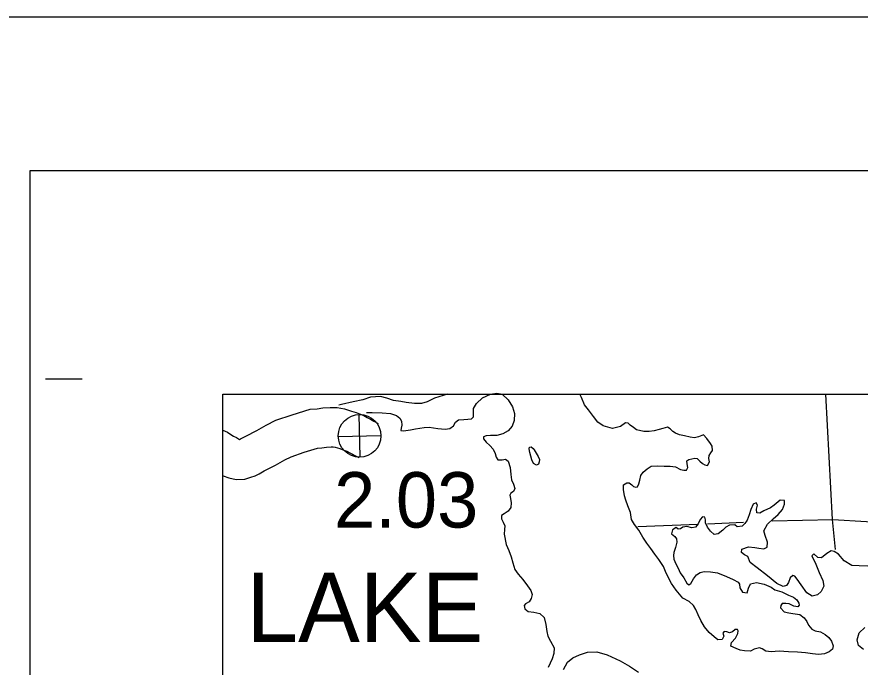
# Model space of a CAD drawing. Extents: x 22866 to 28196, y 1324810 to 1328105.
# Drawn here: x 23880.5 to 24094.2, y 1327377.1 to 1327541.9 of the extents above; entities that cross this region are included whole.
import ezdxf

# ---------------------------------------------------------------- set-up
doc = ezdxf.new("R2010")
doc.units = 0
for name, color, linetype in [('Level 10', 7, 'Continuous'), ('Level 25', 7, 'Continuous'), ('Level 26', 7, 'Continuous'), ('Level 5', 7, 'Continuous'), ('Level 7', 7, 'Continuous'), ('Level 9', 7, 'Continuous'), ('R_Border', 7, 'Continuous'), ('R_No Plot', 7, 'Continuous')]:
    doc.layers.add(name, color=color, linetype=linetype)

msp = doc.modelspace()

# ---------------------------------------------------------------- linework, layer by layer
at = {"layer": 'Level 10'}
for points in [[(23932.69, 1327437.11), (23933.86, 1327436.62), (23935.03, 1327435.9), (23935.43, 1327435.63), (23936.18, 1327435.25), (23936.91, 1327434.82), (23937.22, 1327434.91), (23938.53, 1327435.65), (23941.35, 1327437.05), (23943.68, 1327438.39), (23946.13, 1327439.65), (23950.26, 1327441.02), (23954.87, 1327442.45), (23956.63, 1327442.58), (23958.02, 1327442.8), (23959.89, 1327442.89), (23961.72, 1327442.89), (23963.53, 1327442.52), (23965.36, 1327442), (23966.49, 1327441.61), (23967.37, 1327441.25), (23968.41, 1327440.83), (23969.3, 1327440.35), (23970.16, 1327439.97), (23971.01, 1327439.46), (23972.08, 1327438.85)], [(23932.69, 1327437.11), (23933.86, 1327436.62), (23935.03, 1327435.9), (23935.43, 1327435.63), (23936.18, 1327435.25), (23936.91, 1327434.82), (23937.22, 1327434.91), (23938.53, 1327435.65), (23941.35, 1327437.05), (23943.68, 1327438.39), (23946.13, 1327439.65), (23950.26, 1327441.02), (23954.87, 1327442.45), (23956.63, 1327442.58), (23958.02, 1327442.8), (23959.89, 1327442.89), (23961.72, 1327442.89), (23963.53, 1327442.52), (23965.36, 1327442), (23966.49, 1327441.61), (23967.37, 1327441.25), (23968.41, 1327440.83), (23969.3, 1327440.35), (23970.16, 1327439.97), (23971.01, 1327439.46), (23972.08, 1327438.85)], [(23932.69, 1327425.69), (23932.83, 1327425.6), (23934.2, 1327425.04), (23936.11, 1327424.62), (23938.28, 1327424.77), (23939.78, 1327425.27), (23940.89, 1327425.59), (23941.89, 1327426.1), (23943.19, 1327426.83), (23946.07, 1327428.25), (23948.45, 1327429.63), (23950, 1327430.42), (23953.31, 1327431.53), (23956.75, 1327432.59), (23957.77, 1327432.67), (23959.03, 1327432.86), (23960.14, 1327432.92), (23960.7, 1327432.92), (23961.17, 1327432.82), (23962.35, 1327432.49), (23962.97, 1327432.27), (23963.64, 1327432), (23964.14, 1327431.8), (23964.87, 1327431.4), (23965.56, 1327431.09), (23965.99, 1327430.84), (23967.15, 1327430.18)], [(23932.69, 1327425.69), (23932.83, 1327425.6), (23934.2, 1327425.04), (23936.11, 1327424.62), (23938.28, 1327424.77), (23939.78, 1327425.27), (23940.89, 1327425.59), (23941.89, 1327426.1), (23943.19, 1327426.83), (23946.07, 1327428.25), (23948.45, 1327429.63), (23950, 1327430.42), (23953.31, 1327431.53), (23956.75, 1327432.59), (23957.77, 1327432.67), (23959.03, 1327432.86), (23960.14, 1327432.92), (23960.7, 1327432.92), (23961.17, 1327432.82), (23962.35, 1327432.49), (23962.97, 1327432.27), (23963.64, 1327432), (23964.14, 1327431.8), (23964.87, 1327431.4), (23965.56, 1327431.09), (23965.99, 1327430.84), (23967.15, 1327430.18)]]:
    msp.add_lwpolyline(points, dxfattribs=at)
at = {"layer": 'Level 26'}
for p, q in [((23967.52, 1327430.29), (23967.27, 1327441.11)), ((23967.52, 1327430.29), (23967.27, 1327441.11)), ((23961.98, 1327435.58), (23972.8, 1327435.83)), ((23961.98, 1327435.58), (23972.8, 1327435.83))]:
    msp.add_line(p, q, dxfattribs=at)
msp.add_circle((23967.39, 1327435.7), 5.41, dxfattribs=at)
msp.add_circle((23967.39, 1327435.7), 5.41, dxfattribs=at)
at = {"layer": 'Level 5'}
for points in [[(24085.48, 1327446.26), (24087.12, 1327414.51), (24087.9, 1327406.87)], [(24085.48, 1327446.26), (24087.12, 1327414.51), (24087.9, 1327406.87)], [(24164.15, 1327409.88), (24087.29, 1327414.41), (24071.91, 1327414.08)], [(24164.15, 1327409.88), (24087.29, 1327414.41), (24071.91, 1327414.08)], [(24053.06, 1327413.25), (24037.92, 1327412.66)], [(24053.06, 1327413.25), (24037.92, 1327412.66)], [(24064.64, 1327413.78), (24055.58, 1327413.29)], [(24064.64, 1327413.78), (24055.58, 1327413.29)]]:
    msp.add_lwpolyline(points, dxfattribs=at)
at = {"layer": 'Level 7'}
msp.add_lwpolyline([(23897.05, 1327450.11), (23887.75, 1327450.07)], dxfattribs=at)
at = {"layer": 'Level 9'}
for points in [[(23969.14, 1327441.6), (23970.58, 1327441.66), (23973.11, 1327441.55), (23975.21, 1327441.39), (23976.75, 1327440.89), (23977.56, 1327440.15), (23977.98, 1327439.39), (23978.1, 1327438.42), (23977.95, 1327437.66), (23977.83, 1327437.05), (23978.53, 1327436.97), (23980.28, 1327437.27), (23981.58, 1327437.47), (23983.73, 1327437.85), (23985.03, 1327437.91), (23987.2, 1327437.55), (23989.09, 1327437.39), (23990.25, 1327437.55), (23991.17, 1327438.27), (23991.72, 1327439.15), (23992.47, 1327439.73), (23993.83, 1327439.86), (23994.83, 1327439.95), (23995.75, 1327440.03), (23996.28, 1327440.55), (23996.28, 1327441.78), (23996.23, 1327442.68), (23996.97, 1327443.92), (23998.53, 1327445.32), (24000.58, 1327446.27), (24002.17, 1327446.5), (24003.47, 1327446.26), (24005.06, 1327444.83), (24006.1, 1327443.09), (24006.6, 1327441.37), (24006.54, 1327439.63), (24006.07, 1327438.19), (24005, 1327437), (24003.72, 1327436.24), (24002.16, 1327435.81), (24000.57, 1327435.81), (23999.44, 1327435.68), (23998.78, 1327435.5), (23998.76, 1327434.97), (23999.44, 1327434.08), (24000.36, 1327433.27), (24001.21, 1327432.36), (24001.73, 1327431.27), (24001.95, 1327430.27), (24002.43, 1327429.62), (24003.49, 1327429.67), (24004.32, 1327429.76), (24005, 1327429.27), (24005.56, 1327427.72), (24005.7, 1327425.89), (24005.86, 1327424.53)], [(23969.14, 1327441.6), (23970.58, 1327441.66), (23973.11, 1327441.55), (23975.21, 1327441.39), (23976.75, 1327440.89), (23977.56, 1327440.15), (23977.98, 1327439.39), (23978.1, 1327438.42), (23977.95, 1327437.66), (23977.83, 1327437.05), (23978.53, 1327436.97), (23980.28, 1327437.27), (23981.58, 1327437.47), (23983.73, 1327437.85), (23985.03, 1327437.91), (23987.2, 1327437.55), (23989.09, 1327437.39), (23990.25, 1327437.55), (23991.17, 1327438.27), (23991.72, 1327439.15), (23992.47, 1327439.73), (23993.83, 1327439.86), (23994.83, 1327439.95), (23995.75, 1327440.03), (23996.28, 1327440.55), (23996.28, 1327441.78), (23996.23, 1327442.68), (23996.97, 1327443.92), (23998.53, 1327445.32), (24000.58, 1327446.27), (24002.17, 1327446.5), (24003.47, 1327446.26), (24005.06, 1327444.83), (24006.1, 1327443.09), (24006.6, 1327441.37), (24006.54, 1327439.63), (24006.07, 1327438.19), (24005, 1327437), (24003.72, 1327436.24), (24002.16, 1327435.81), (24000.57, 1327435.81), (23999.44, 1327435.68), (23998.78, 1327435.5), (23998.76, 1327434.97), (23999.44, 1327434.08), (24000.36, 1327433.27), (24001.21, 1327432.36), (24001.73, 1327431.27), (24001.95, 1327430.27), (24002.43, 1327429.62), (24003.49, 1327429.67), (24004.32, 1327429.76), (24005, 1327429.27), (24005.56, 1327427.72), (24005.7, 1327425.89), (24005.86, 1327424.53)], [(23989.54, 1327446.26), (23988.54, 1327445.94), (23986.4, 1327445.26), (23984.52, 1327444.29), (23983.04, 1327443.89), (23981.27, 1327443.89), (23979.17, 1327444.18), (23977.8, 1327444.38), (23975.97, 1327444.64), (23974.26, 1327445.27), (23972.69, 1327445.67), (23970.16, 1327445.48), (23968.22, 1327444.81), (23965.77, 1327444.32), (23962.79, 1327443.66), (23962.09, 1327443.47)], [(23989.54, 1327446.26), (23988.54, 1327445.94), (23986.4, 1327445.26), (23984.52, 1327444.29), (23983.04, 1327443.89), (23981.27, 1327443.89), (23979.17, 1327444.18), (23977.8, 1327444.38), (23975.97, 1327444.64), (23974.26, 1327445.27), (23972.69, 1327445.67), (23970.16, 1327445.48), (23968.22, 1327444.81), (23965.77, 1327444.32), (23962.79, 1327443.66), (23962.09, 1327443.47)], [(24025.43, 1327442.34), (24024.38, 1327443.58), (24023.6, 1327445.46), (24023.22, 1327446.26)], [(24025.43, 1327442.34), (24024.38, 1327443.58), (24023.6, 1327445.46), (24023.22, 1327446.26)], [(24063.14, 1327386.65), (24062.58, 1327386.6), (24061.86, 1327386.02), (24061.13, 1327385.8), (24060.46, 1327386.06), (24059.76, 1327386.14), (24059.41, 1327385.67), (24059.69, 1327384.91), (24059.24, 1327384.13), (24058.18, 1327383.98), (24057.23, 1327384.75), (24055.94, 1327385.86), (24054.75, 1327387.33), (24053.85, 1327388.88), (24053.15, 1327390.33), (24052.63, 1327391.68), (24052.01, 1327392.74), (24050.89, 1327393.71), (24049.34, 1327394.61), (24047.57, 1327396.61), (24046.43, 1327398.28), (24045.11, 1327400.92), (24044.41, 1327402.63), (24043.18, 1327404.34), (24042.22, 1327405.69), (24041.15, 1327407.16), (24040.16, 1327408.51), (24039.2, 1327410.02), (24038.13, 1327411.79), (24037.03, 1327413.24), (24036.27, 1327414.49), (24036, 1327416.31), (24035.34, 1327417.96), (24034.84, 1327419.39), (24034.55, 1327420.51), (24034.22, 1327422.1), (24034.22, 1327423.27), (24035.08, 1327423.82), (24035.74, 1327423.8), (24036.38, 1327423.32), (24036.76, 1327422.89), (24037.43, 1327422.71), (24037.79, 1327422.78), (24038.11, 1327423.55), (24038.39, 1327424.46), (24038.69, 1327425.66), (24039.27, 1327426.51), (24040.29, 1327427.36), (24041.3, 1327428.02), (24042.86, 1327428.12), (24044.53, 1327428.05), (24046.06, 1327427.99), (24047.46, 1327427.88), (24048.74, 1327427.21), (24049.54, 1327427.03), (24050.2, 1327427.01), (24050.59, 1327427.72), (24050.4, 1327428.61), (24050.29, 1327429.38), (24050.81, 1327429.72), (24051.54, 1327429.9), (24052.3, 1327430.05), (24052.93, 1327429.97), (24053.58, 1327429.31), (24054.29, 1327428.66), (24054.86, 1327428.34), (24055.53, 1327428.16), (24056.08, 1327429.13), (24055.93, 1327429.93), (24055.98, 1327430.7), (24056.43, 1327431.37), (24056.78, 1327432.01), (24056.72, 1327433.08), (24056.28, 1327433.8), (24055.35, 1327435.05), (24054.57, 1327435.96), (24053.28, 1327435.5), (24052.26, 1327435.21), (24051.19, 1327435.36), (24049.68, 1327435.73), (24048.42, 1327435.93), (24047.44, 1327436.41), (24046.8, 1327436.8), (24046.09, 1327437.45), (24045.42, 1327437.87), (24044.26, 1327437.61), (24043.33, 1327437.32), (24042.01, 1327436.96), (24040.75, 1327436.83), (24039.39, 1327436.84), (24037.58, 1327437.23), (24036.77, 1327437.81), (24035.96, 1327438.43), (24035.45, 1327438.95), (24034.78, 1327438.97), (24033.54, 1327438.08), (24031.49, 1327437.53), (24029.08, 1327438.22), (24027.76, 1327439.19), (24026.7, 1327440.63), (24025.43, 1327442.34)], [(24063.14, 1327386.65), (24062.58, 1327386.6), (24061.86, 1327386.02), (24061.13, 1327385.8), (24060.46, 1327386.06), (24059.76, 1327386.14), (24059.41, 1327385.67), (24059.69, 1327384.91), (24059.24, 1327384.13), (24058.18, 1327383.98), (24057.23, 1327384.75), (24055.94, 1327385.86), (24054.75, 1327387.33), (24053.85, 1327388.88), (24053.15, 1327390.33), (24052.63, 1327391.68), (24052.01, 1327392.74), (24050.89, 1327393.71), (24049.34, 1327394.61), (24047.57, 1327396.61), (24046.43, 1327398.28), (24045.11, 1327400.92), (24044.41, 1327402.63), (24043.18, 1327404.34), (24042.22, 1327405.69), (24041.15, 1327407.16), (24040.16, 1327408.51), (24039.2, 1327410.02), (24038.13, 1327411.79), (24037.03, 1327413.24), (24036.27, 1327414.49), (24036, 1327416.31), (24035.34, 1327417.96), (24034.84, 1327419.39), (24034.55, 1327420.51), (24034.22, 1327422.1), (24034.22, 1327423.27), (24035.08, 1327423.82), (24035.74, 1327423.8), (24036.38, 1327423.32), (24036.76, 1327422.89), (24037.43, 1327422.71), (24037.79, 1327422.78), (24038.11, 1327423.55), (24038.39, 1327424.46), (24038.69, 1327425.66), (24039.27, 1327426.51), (24040.29, 1327427.36), (24041.3, 1327428.02), (24042.86, 1327428.12), (24044.53, 1327428.05), (24046.06, 1327427.99), (24047.46, 1327427.88), (24048.74, 1327427.21), (24049.54, 1327427.03), (24050.2, 1327427.01), (24050.59, 1327427.72), (24050.4, 1327428.61), (24050.29, 1327429.38), (24050.81, 1327429.72), (24051.54, 1327429.9), (24052.3, 1327430.05), (24052.93, 1327429.97), (24053.58, 1327429.31), (24054.29, 1327428.66), (24054.86, 1327428.34), (24055.53, 1327428.16), (24056.08, 1327429.13), (24055.93, 1327429.93), (24055.98, 1327430.7), (24056.43, 1327431.37), (24056.78, 1327432.01), (24056.72, 1327433.08), (24056.28, 1327433.8), (24055.35, 1327435.05), (24054.57, 1327435.96), (24053.28, 1327435.5), (24052.26, 1327435.21), (24051.19, 1327435.36), (24049.68, 1327435.73), (24048.42, 1327435.93), (24047.44, 1327436.41), (24046.8, 1327436.8), (24046.09, 1327437.45), (24045.42, 1327437.87), (24044.26, 1327437.61), (24043.33, 1327437.32), (24042.01, 1327436.96), (24040.75, 1327436.83), (24039.39, 1327436.84), (24037.58, 1327437.23), (24036.77, 1327437.81), (24035.96, 1327438.43), (24035.45, 1327438.95), (24034.78, 1327438.97), (24033.54, 1327438.08), (24031.49, 1327437.53), (24029.08, 1327438.22), (24027.76, 1327439.19), (24026.7, 1327440.63), (24025.43, 1327442.34)], [(24012.62, 1327430.44), (24013, 1327429.71), (24012.91, 1327429.14), (24012.73, 1327428.54), (24012.2, 1327428.29), (24011.43, 1327428.68), (24011.01, 1327429.6), (24010.76, 1327430.53), (24010.54, 1327431.46), (24010.35, 1327432.39), (24010.41, 1327432.82), (24010.9, 1327432.93), (24011.35, 1327432.51), (24011.62, 1327432.18)], [(24012.62, 1327430.44), (24013, 1327429.71), (24012.91, 1327429.14), (24012.73, 1327428.54), (24012.2, 1327428.29), (24011.43, 1327428.68), (24011.01, 1327429.6), (24010.76, 1327430.53), (24010.54, 1327431.46), (24010.35, 1327432.39), (24010.41, 1327432.82), (24010.9, 1327432.93), (24011.35, 1327432.51), (24011.62, 1327432.18)], [(24011.62, 1327432.18), (24012.62, 1327430.44)], [(24011.62, 1327432.18), (24012.62, 1327430.44)], [(24005.86, 1327424.53), (24006.42, 1327423.44), (24006.71, 1327422.35), (24006.39, 1327421.64), (24005.7, 1327421.16), (24005.45, 1327420.66), (24005.6, 1327419.79), (24005.82, 1327418.7), (24005.68, 1327417.56), (24005.04, 1327416.65), (24004.05, 1327415.96), (24003.3, 1327415.55), (24003.35, 1327414.65), (24003.77, 1327413.82), (24004.22, 1327412.93), (24004.11, 1327411.97), (24004.03, 1327410.76), (24004.52, 1327408.21), (24005.22, 1327406.63), (24005.75, 1327405.07), (24006.25, 1327403.52), (24006.75, 1327401.86), (24007.57, 1327400.68), (24008.77, 1327399.31), (24009.97, 1327397.67), (24010.76, 1327396.52), (24011.08, 1327395.53), (24010.87, 1327394.52), (24010.32, 1327393.68), (24009.4, 1327393.13), (24009.08, 1327392.72), (24009.23, 1327391.89), (24010.07, 1327391.21), (24011.54, 1327391.01), (24013.04, 1327390.64), (24014.16, 1327389.7), (24014.57, 1327387.87), (24014.87, 1327386.11), (24015.06, 1327384.92), (24015.72, 1327383.67), (24016.66, 1327381.99), (24016.62, 1327380.52), (24016.15, 1327379.21), (24015.2, 1327376.96)], [(24005.86, 1327424.53), (24006.42, 1327423.44), (24006.71, 1327422.35), (24006.39, 1327421.64), (24005.7, 1327421.16), (24005.45, 1327420.66), (24005.6, 1327419.79), (24005.82, 1327418.7), (24005.68, 1327417.56), (24005.04, 1327416.65), (24004.05, 1327415.96), (24003.3, 1327415.55), (24003.35, 1327414.65), (24003.77, 1327413.82), (24004.22, 1327412.93), (24004.11, 1327411.97), (24004.03, 1327410.76), (24004.52, 1327408.21), (24005.22, 1327406.63), (24005.75, 1327405.07), (24006.25, 1327403.52), (24006.75, 1327401.86), (24007.57, 1327400.68), (24008.77, 1327399.31), (24009.97, 1327397.67), (24010.76, 1327396.52), (24011.08, 1327395.53), (24010.87, 1327394.52), (24010.32, 1327393.68), (24009.4, 1327393.13), (24009.08, 1327392.72), (24009.23, 1327391.89), (24010.07, 1327391.21), (24011.54, 1327391.01), (24013.04, 1327390.64), (24014.16, 1327389.7), (24014.57, 1327387.87), (24014.87, 1327386.11), (24015.06, 1327384.92), (24015.72, 1327383.67), (24016.66, 1327381.99), (24016.62, 1327380.52), (24016.15, 1327379.21), (24015.2, 1327376.96)], [(24096.22, 1327402.64), (24093.99, 1327402.76), (24092.09, 1327402.86), (24090.2, 1327404.05), (24088.74, 1327405.68), (24087.66, 1327406.36), (24086.86, 1327406.57), (24085.81, 1327405.92), (24084.47, 1327404.79), (24083.54, 1327404.87), (24082.52, 1327405.82), (24081.96, 1327405.3), (24082.97, 1327403.16), (24083.88, 1327401.08), (24084.82, 1327399.07), (24085.05, 1327397.64), (24084.39, 1327396.26), (24083.44, 1327395.41), (24082.12, 1327395.08), (24080.74, 1327395.88), (24079.26, 1327397.92), (24078.3, 1327399.4), (24077.72, 1327400.18), (24077.18, 1327400.34), (24076.5, 1327399.76), (24076.12, 1327398.52), (24075.54, 1327397.77), (24074.75, 1327397.52), (24073.1, 1327398.32), (24070.77, 1327400.2), (24068.16, 1327402.24), (24066.37, 1327403.57), (24065.77, 1327405.09), (24064.96, 1327405.57), (24064.15, 1327406.16), (24064.27, 1327406.99), (24065.92, 1327407.59), (24067.55, 1327407.43), (24068.59, 1327407.25), (24069.85, 1327407.11), (24070.71, 1327407.53), (24070.75, 1327408.76), (24070.15, 1327410.41), (24069.86, 1327411.61), (24070.75, 1327413.33), (24072.22, 1327414.66), (24073.49, 1327415.78), (24074.56, 1327417.07), (24075.1, 1327418.41), (24075.04, 1327419.28), (24073.98, 1327419.42), (24072.41, 1327418.12), (24071.49, 1327417.47), (24069.81, 1327416.67), (24068.8, 1327416.08), (24068.06, 1327416.2), (24068.01, 1327417.13), (24068.25, 1327418.17), (24067.87, 1327418.69), (24067.12, 1327418.38), (24066.51, 1327417), (24066.08, 1327415.66), (24065.57, 1327414.35), (24064.99, 1327413.5), (24064.31, 1327412.82), (24063.05, 1327412.63), (24062.47, 1327413.15), (24061.15, 1327413.05), (24060.19, 1327412.53), (24059.41, 1327411.82), (24058.27, 1327410.89), (24057.27, 1327410.74), (24056.29, 1327411.55)], [(24096.22, 1327402.64), (24093.99, 1327402.76), (24092.09, 1327402.86), (24090.2, 1327404.05), (24088.74, 1327405.68), (24087.66, 1327406.36), (24086.86, 1327406.57), (24085.81, 1327405.92), (24084.47, 1327404.79), (24083.54, 1327404.87), (24082.52, 1327405.82), (24081.96, 1327405.3), (24082.97, 1327403.16), (24083.88, 1327401.08), (24084.82, 1327399.07), (24085.05, 1327397.64), (24084.39, 1327396.26), (24083.44, 1327395.41), (24082.12, 1327395.08), (24080.74, 1327395.88), (24079.26, 1327397.92), (24078.3, 1327399.4), (24077.72, 1327400.18), (24077.18, 1327400.34), (24076.5, 1327399.76), (24076.12, 1327398.52), (24075.54, 1327397.77), (24074.75, 1327397.52), (24073.1, 1327398.32), (24070.77, 1327400.2), (24068.16, 1327402.24), (24066.37, 1327403.57), (24065.77, 1327405.09), (24064.96, 1327405.57), (24064.15, 1327406.16), (24064.27, 1327406.99), (24065.92, 1327407.59), (24067.55, 1327407.43), (24068.59, 1327407.25), (24069.85, 1327407.11), (24070.71, 1327407.53), (24070.75, 1327408.76), (24070.15, 1327410.41), (24069.86, 1327411.61), (24070.75, 1327413.33), (24072.22, 1327414.66), (24073.49, 1327415.78), (24074.56, 1327417.07), (24075.1, 1327418.41), (24075.04, 1327419.28), (24073.98, 1327419.42), (24072.41, 1327418.12), (24071.49, 1327417.47), (24069.81, 1327416.67), (24068.8, 1327416.08), (24068.06, 1327416.2), (24068.01, 1327417.13), (24068.25, 1327418.17), (24067.87, 1327418.69), (24067.12, 1327418.38), (24066.51, 1327417), (24066.08, 1327415.66), (24065.57, 1327414.35), (24064.99, 1327413.5), (24064.31, 1327412.82), (24063.05, 1327412.63), (24062.47, 1327413.15), (24061.15, 1327413.05), (24060.19, 1327412.53), (24059.41, 1327411.82), (24058.27, 1327410.89), (24057.27, 1327410.74), (24056.29, 1327411.55)], [(24056.29, 1327411.55), (24055.54, 1327412.6), (24055.01, 1327413.65), (24055.03, 1327414.42), (24054.88, 1327415.08), (24054.25, 1327415.14), (24053.73, 1327414.53), (24053.19, 1327413.38), (24052.54, 1327412.54), (24051.58, 1327412.38), (24050.31, 1327412.69), (24049.28, 1327412.57), (24048.69, 1327412.15), (24048.13, 1327412.04), (24047.59, 1327412.46), (24046.64, 1327411.88), (24046.46, 1327410.91), (24047.24, 1327410.19), (24047.72, 1327409.63), (24047.74, 1327408.77), (24047.43, 1327407.43), (24047.03, 1327406.16), (24046.95, 1327405.35), (24047.06, 1327404.49), (24047.49, 1327403.27), (24048.08, 1327402.21), (24048.6, 1327401.03), (24049.56, 1327399.75), (24050.35, 1327398.37), (24050.8, 1327397.94), (24051.32, 1327398.25), (24051.99, 1327399.43), (24052.77, 1327400.45), (24053.72, 1327401.04), (24054.68, 1327401.29), (24056.34, 1327401.26), (24058.05, 1327400.96), (24060.39, 1327400.08), (24062.07, 1327399.32), (24063.32, 1327398.61), (24063.63, 1327398.12), (24063.72, 1327397.15), (24064.44, 1327396.13), (24065.57, 1327395.89), (24065.91, 1327397.13), (24066.42, 1327398.24), (24068.01, 1327398.51), (24069.95, 1327398.12), (24071.69, 1327397.32), (24072.6, 1327396.68), (24074.35, 1327396.15), (24076.09, 1327395.35), (24077.37, 1327394.78), (24078.15, 1327394.16), (24078.73, 1327393.34), (24078.77, 1327392.78), (24078.45, 1327392.37), (24077.42, 1327392.55), (24076.24, 1327393.12), (24075.41, 1327393.2), (24074.51, 1327393.19), (24074.12, 1327392.74), (24074.07, 1327392.08), (24074.95, 1327391.1), (24076.15, 1327390.86), (24077.19, 1327390.68), (24078.99, 1327390.45), (24080.04, 1327389.61), (24080.69, 1327388.69), (24081.11, 1327387.76), (24082, 1327386.72), (24082.84, 1327386.3), (24084.21, 1327386.06), (24085.35, 1327385.32), (24086.3, 1327384.61), (24086.98, 1327383.66), (24087.44, 1327382.47), (24087.26, 1327381.67), (24086.41, 1327380.98), (24085.19, 1327380.49), (24083.67, 1327380.26), (24082.2, 1327380.43), (24080.43, 1327380.69), (24078.33, 1327380.84), (24076.07, 1327380.93), (24073.7, 1327381.14), (24071.71, 1327380.97), (24070.35, 1327381.1), (24069.37, 1327381.75), (24068.7, 1327382), (24067.34, 1327381.64), (24066.45, 1327381.12), (24064.92, 1327381.22), (24063.79, 1327381.4), (24062.78, 1327381.81), (24061.44, 1327382.41), (24061.62, 1327383.32), (24062.62, 1327384.47), (24063.2, 1327385.62), (24063.35, 1327386.28), (24063.14, 1327386.65)], [(24056.29, 1327411.55), (24055.54, 1327412.6), (24055.01, 1327413.65), (24055.03, 1327414.42), (24054.88, 1327415.08), (24054.25, 1327415.14), (24053.73, 1327414.53), (24053.19, 1327413.38), (24052.54, 1327412.54), (24051.58, 1327412.38), (24050.31, 1327412.69), (24049.28, 1327412.57), (24048.69, 1327412.15), (24048.13, 1327412.04), (24047.59, 1327412.46), (24046.64, 1327411.88), (24046.46, 1327410.91), (24047.24, 1327410.19), (24047.72, 1327409.63), (24047.74, 1327408.77), (24047.43, 1327407.43), (24047.03, 1327406.16), (24046.95, 1327405.35), (24047.06, 1327404.49), (24047.49, 1327403.27), (24048.08, 1327402.21), (24048.6, 1327401.03), (24049.56, 1327399.75), (24050.35, 1327398.37), (24050.8, 1327397.94), (24051.32, 1327398.25), (24051.99, 1327399.43), (24052.77, 1327400.45), (24053.72, 1327401.04), (24054.68, 1327401.29), (24056.34, 1327401.26), (24058.05, 1327400.96), (24060.39, 1327400.08), (24062.07, 1327399.32), (24063.32, 1327398.61), (24063.63, 1327398.12), (24063.72, 1327397.15), (24064.44, 1327396.13), (24065.57, 1327395.89), (24065.91, 1327397.13), (24066.42, 1327398.24), (24068.01, 1327398.51), (24069.95, 1327398.12), (24071.69, 1327397.32), (24072.6, 1327396.68), (24074.35, 1327396.15), (24076.09, 1327395.35), (24077.37, 1327394.78), (24078.15, 1327394.16), (24078.73, 1327393.34), (24078.77, 1327392.78), (24078.45, 1327392.37), (24077.42, 1327392.55), (24076.24, 1327393.12), (24075.41, 1327393.2), (24074.51, 1327393.19), (24074.12, 1327392.74), (24074.07, 1327392.08), (24074.95, 1327391.1), (24076.15, 1327390.86), (24077.19, 1327390.68), (24078.99, 1327390.45), (24080.04, 1327389.61), (24080.69, 1327388.69), (24081.11, 1327387.76), (24082, 1327386.72), (24082.84, 1327386.3), (24084.21, 1327386.06), (24085.35, 1327385.32), (24086.3, 1327384.61), (24086.98, 1327383.66), (24087.44, 1327382.47), (24087.26, 1327381.67), (24086.41, 1327380.98), (24085.19, 1327380.49), (24083.67, 1327380.26), (24082.2, 1327380.43), (24080.43, 1327380.69), (24078.33, 1327380.84), (24076.07, 1327380.93), (24073.7, 1327381.14), (24071.71, 1327380.97), (24070.35, 1327381.1), (24069.37, 1327381.75), (24068.7, 1327382), (24067.34, 1327381.64), (24066.45, 1327381.12), (24064.92, 1327381.22), (24063.79, 1327381.4), (24062.78, 1327381.81), (24061.44, 1327382.41), (24061.62, 1327383.32), (24062.62, 1327384.47), (24063.2, 1327385.62), (24063.35, 1327386.28), (24063.14, 1327386.65)], [(24095.08, 1327381.6), (24093.82, 1327382.61), (24093.5, 1327383.97), (24094.02, 1327385.74), (24095.42, 1327387.17)], [(24095.08, 1327381.6), (24093.82, 1327382.61), (24093.5, 1327383.97), (24094.02, 1327385.74), (24095.42, 1327387.17)], [(24019.07, 1327376.48), (24020.09, 1327378.33), (24021.4, 1327379.46), (24023.14, 1327380.19), (24025.13, 1327380.84), (24027.52, 1327380.95), (24030.16, 1327380.21), (24033.45, 1327378.65), (24035.78, 1327377.37), (24038.1, 1327375.82)], [(24019.07, 1327376.48), (24020.09, 1327378.33), (24021.4, 1327379.46), (24023.14, 1327380.19), (24025.13, 1327380.84), (24027.52, 1327380.95), (24030.16, 1327380.21), (24033.45, 1327378.65), (24035.78, 1327377.37), (24038.1, 1327375.82)]]:
    msp.add_lwpolyline(points, dxfattribs=at)
at = {"layer": 'R_Border'}
for p, q in [((23883.86, 1327502.95), (27045.59, 1327502.95)), ((23883.86, 1325448.4), (23883.86, 1327502.95))]:
    msp.add_line(p, q, dxfattribs=at)
at = {"layer": 'R_No Plot'}
msp.add_line((23759.85, 1327541.9), (27093.11, 1327541.9), dxfattribs=at)
for points in [[(23759.79, 1327541.9), (27093.11, 1327541.9), (27093.11, 1325408.57), (23759.79, 1325408.57)], [(23932.69, 1327446.26), (24728.44, 1327446.26), (24728.44, 1326652.92), (23932.69, 1326652.92)]]:
    msp.add_lwpolyline(points, close=True, dxfattribs=at)

# ---------------------------------------------------------------- texts
at = {"layer": 'Level 25'}
msp.add_text('2.03', height=14.044, dxfattribs=at).set_placement((23960.91, 1327412.46))
msp.add_text('2.03', height=14.044, dxfattribs=at).set_placement((23960.91, 1327412.46))
at = {"layer": 'Level 7'}
msp.add_text('LAKE', height=17.555, dxfattribs=at).set_placement((23938.73, 1327383.44))
msp.add_text('LAKE', height=17.555, dxfattribs=at).set_placement((23938.73, 1327383.44))

doc.saveas('drawing.dxf')
